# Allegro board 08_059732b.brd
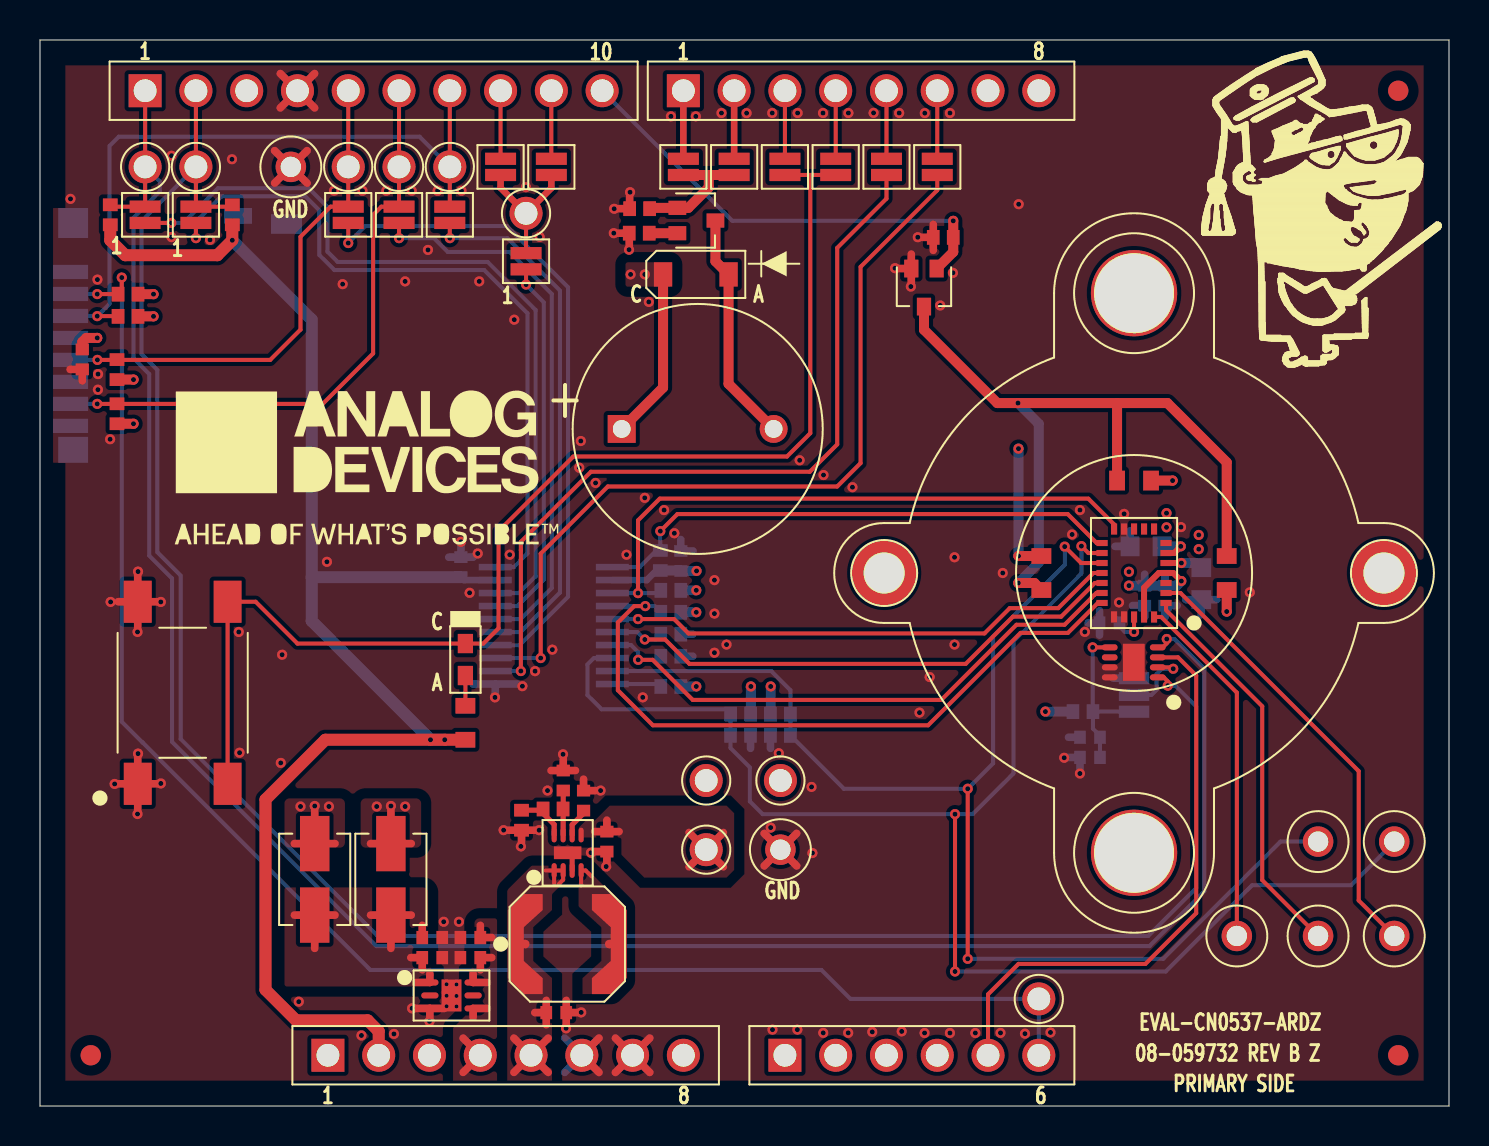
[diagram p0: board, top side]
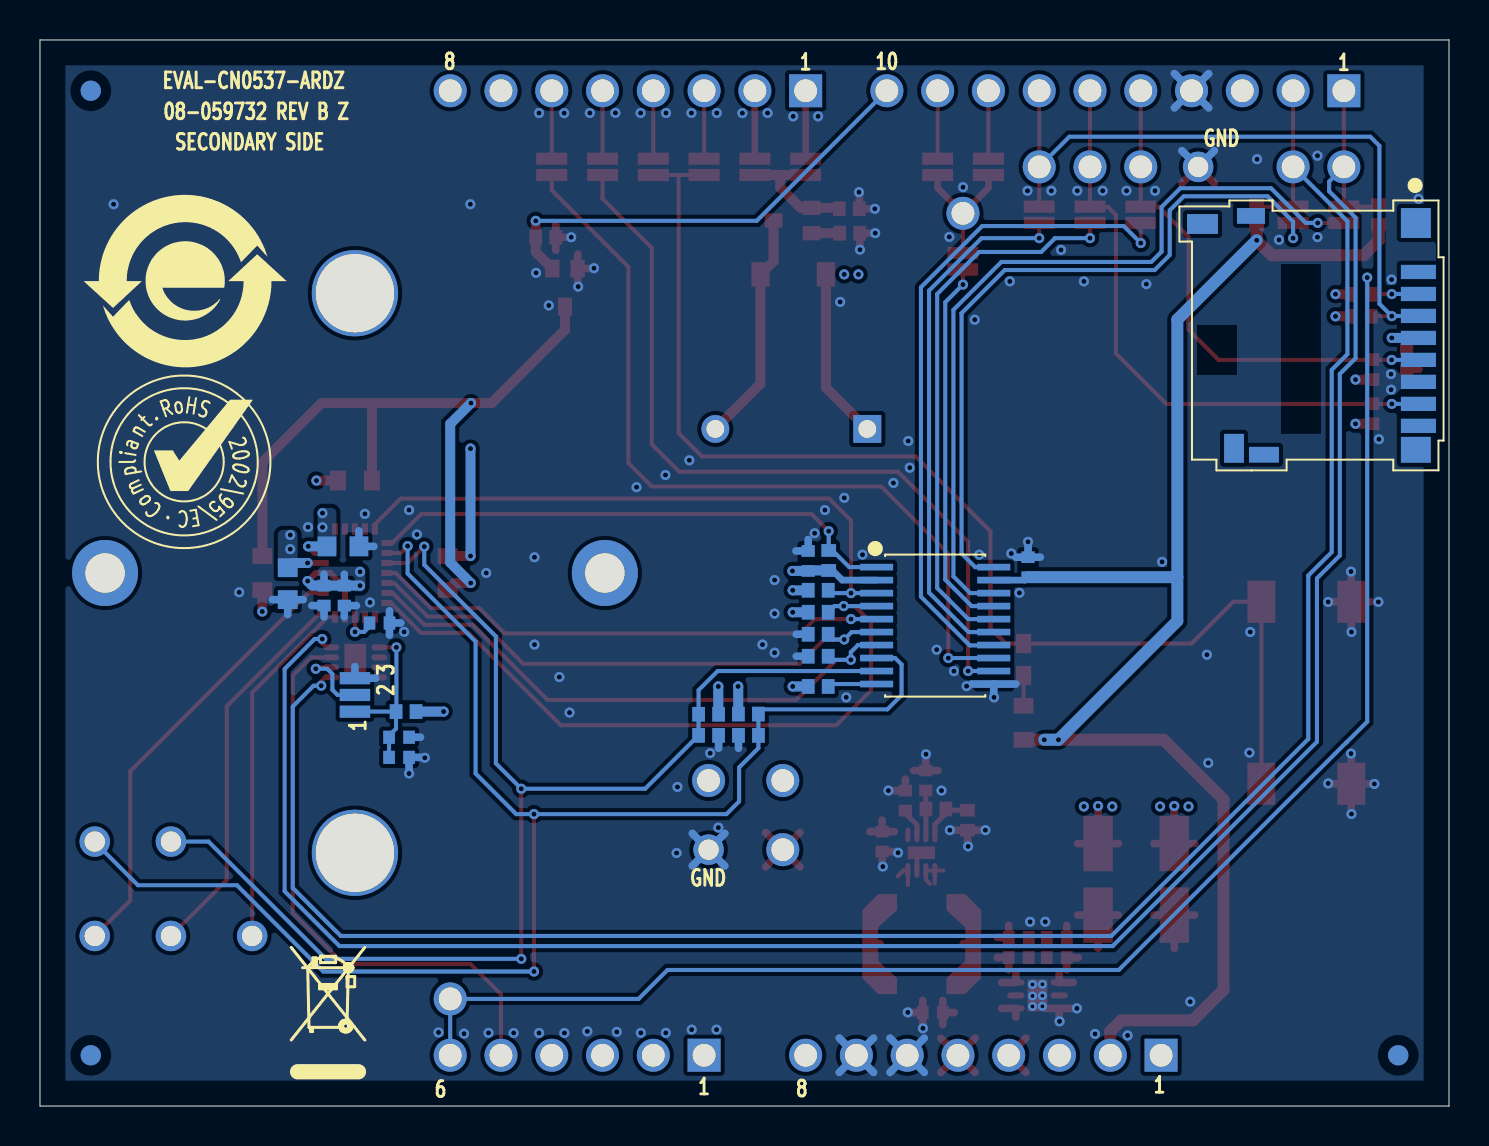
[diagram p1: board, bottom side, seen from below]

Outline 70.48 x 53.34 mm; copper layers: TOP, L2_GND, L3_PWR, BOTTOM. Coordinates in mm from the lower left corner of the outline.
Outline path: 0,53.34 0,0 70.48,0 70.48,53.34 0,53.34

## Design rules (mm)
constraint set DEFAULT: min track width 0.203

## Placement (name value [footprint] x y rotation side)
C1  10UF  [C0402]  55.26 25.54 270 bottom
C2  0.1uF  [C0402]  56.28 25.54 270 bottom
C3  22uF  [C0603]  58.09 26.14 270 bottom
C4  22uF  [C0603]  55.33 28 180 bottom
C5  1UF  [C0402]  53.5 24.17 180 bottom
C7  0.1uF  [C0402]  32.06 27.27 90 bottom
C8  0.1uF  [C0402]  21.06 26.96 90 bottom
C9  10UF  [C0402]  21.53 8.43 180 top
C10  0.1uF  [C0402]  21.53 7.43 180 top
C11  0.1uF  [C0402]  19.62 7.43 0 top
C12  10UF  [C0402]  19.62 8.43 0 top
C13  2.2uF  [C0402]  25.82 4.68 0 top
C14  0.1uF  [C0402]  27.19 15.28 90 top
C15  0.1uF  [C0402]  26.18 16.29 90 top
C16  1UF  [C0402]  28.36 13.23 270 top
C17  0.1uF  [C0402]  2.12 37.36 270 top
C18  10UF  [C0402]  52.52 17.44 180 bottom
C19  0.1uF  [C0402]  52.52 18.45 180 bottom
CS1  TESTPAD  [TPC65D45]  24.31 44.67 0 top
CS2  TESTPAD  [TPC65D45]  49.96 5.36 0 top
D2  1N4148W-7-F  [SOD123-2]  32.81 41.61 0 top
DS1  APT1608-LSECK-J3-PRV  [LED0603]  21.28 22.34 270 top
E1  42OHM AT 10MEGHZ  [LSML160W120H120]  17.55 11.34 90 top
E2  42OHM AT 10MEGHZ  [LSML160W120H120]  13.74 11.34 90 top
GND1  BLK  [CNKEY5001TP]  37.04 12.83 270 top
GND2  BLK  [CNKEY5001TP]  12.55 46.99 270 top
GPIO0  BLK  [CNKEY5001TP]  67.74 13.23 0 top
GPIO1  BLK  [CNKEY5001TP]  63.93 13.23 180 top
JP1  -  [JPSLD02]  7.8 44.59 90 top
JP2  -  [JPSLD02]  5.26 44.59 90 top
JP3  -  [JPSLD02]  24.31 42.27 90 top
JP4  -  [JPSLD02]  17.96 44.59 90 top
JP5  -  [JPSLD02]  20.5 44.59 90 top
JP6  -  [JPSLD02]  15.42 44.59 90 top
JP7  3PIN_SOLDER_JUMPER  [JPRSLD03]  54.73 20.57 90 bottom
JP12  -  [JPSLD02]  23.04 46.99 270 top
JP13  -  [JPSLD02]  25.58 46.99 270 top
JP14  -  [JPSLD02]  32.18 46.99 270 top
JP15  -  [JPSLD02]  34.72 46.99 270 top
JP16  -  [JPSLD02]  37.26 46.99 270 top
JP17  -  [JPSLD02]  39.8 46.99 270 top
JP18  -  [JPSLD02]  42.34 46.99 270 top
JP19  -  [JPSLD02]  44.88 46.99 270 top
L1  100uH  [LSMSQ189H123]  26.38 8.1 0 top
MISO  TESTPAD  [TPC65D45]  17.96 46.99 0 top
MOSI  TESTPAD  [TPC65D45]  20.5 46.99 0 top
NOREF  -  []  37.36 79.29 0 top
NOREF#2  -  []  60.69 16.84 0 top
NOREF#3  -  []  59.15 30.58 0 top
NOREF#4  -  []  14.4 2.54 0 top
NOREF#5  -  []  70.48 0 90 top
NOREF#6  -  []  70.48 53.34 180 top
NOREF#7  -  []  -143.18 -42.36 0 top
NOREF#8  -  []  56.03 42.13 0 top
NOREF#9  -  []  102.14 40.89 0 top
NOREF#10  -  [unnamed#2]  67.23 26.67 0 top
NOREF#11  -  []  59.69 336.79 0 top
NOREF#12  -  []  70.48 0 90 top
NOREF#13  -  []  24.46 253.81 0 top
NOREF#14  -  []  16.36 31.93 0 top
NOREF#15  -  []  80.7 76.07 0 top
NOREF#16  -  []  0 0 0 top
NOREF#17  -  []  56.69 40.67 0 top
NOREF#18  -  []  57.63 20.52 0 top
NOREF#19  -  []  0 53.34 0 top
NOREF#20  -  []  116.31 170.76 0 top
NOREF#21  -  [unnamed#2]  67.94 50.8 0 top
NOREF#22  -  []  0 53.34 0 top
NOREF#23  -  [unnamed#2]  67.94 2.54 0 top
NOREF#24  -  []  14.4 2.54 0 top
NOREF#25  -  [unnamed#2]  2.54 2.54 0 top
NOREF#26  -  []  75.56 0 0 top
NOREF#27  -  [unnamed#2]  54.73 12.67 0 top
NOREF#28  -  []  0 0 0 top
NOREF#29  -  []  68.11 26.22 0 top
NOREF#30  -  [unnamed#2]  54.73 40.67 0 top
NOREF#31  -  []  0 53.34 270 top
NOREF#32  -  []  62.33 20.17 0 top
NOREF#33  -  []  -41.7 -41.85 0 top
NOREF#34  -  [unnamed#2]  42.23 26.67 0 top
NOREF#35  -  []  0 0 0 top
NOREF#36  -  []  63.22 41.27 180 bottom
NOREF#37  -  []  56.28 1.4 180 bottom
NOREF#38  -  [unnamed#2]  2.54 2.54 180 bottom
NOREF#39  -  []  63.27 32.23 180 bottom
NOREF#40  -  [unnamed#2]  67.94 2.54 180 bottom
NOREF#41  -  [unnamed#2]  67.94 50.8 180 bottom
P1  SSQ-108-03-G-S  [CNSAMTECSSQ-108-XX-X-S]  14.4 2.54 0 top
P2  SSQ-106-03-G-S  [CNSAMTECSSQ-106-XX-X-S]  37.26 2.54 0 top
P3  SSQ-110-03-G-S  [CNSAMTECSSQ-110-XX-X-S]  5.26 50.8 0 top
P4  SSQ-108-03-G-S  [CNSAMTECSSQ-108-XX-X-S]  32.18 50.8 0 top
P5  DM3D-SF  [CNHIROSEDM3D-SF]  6.88 38.57 0 bottom
PD1  BLK  [CNKEY5001TP]  59.87 8.51 0 top
PD2  BLK  [CNKEY5001TP]  67.74 8.51 0 top
PDC  BLK  [CNKEY5001TP]  63.93 8.51 0 top
Q1  DMG1012UW-7  [SOT323]  44.22 40.95 180 top
Q2  DMG1012UW-7  [SOT323]  32.84 44.31 270 top
R2  51K  [R0402]  37.04 19.6 0 bottom
R3  51K  [R0402]  35.05 19.61 180 bottom
R4  51K  [R0402]  37.04 18.55 180 bottom
R5  51K  [R0402]  35.04 18.55 0 bottom
R6  25  [R0603]  54.73 31.29 180 top
R7  25  [R0603]  50.09 26.67 270 top
R9  25  [R0603]  59.36 26.67 90 top
R10  51K  [R0402]  45.18 43.46 180 top
R11  51K  [R0402]  31.03 27.3 90 bottom
R12  51K  [R0402]  31.56 25.8 180 bottom
R13  51K  [R0402]  31.56 24.7 180 bottom
R14  51K  [R0402]  31.56 20.99 180 bottom
R15  51K  [R0402]  31.56 23.6 0 bottom
R16  51K  [R0402]  31.56 22.5 0 bottom
R17  51K  [R0402]  9.62 44.59 90 top
R18  51K  [R0402]  3.52 44.59 90 top
R19  330K  [R0402]  25.67 14.86 180 top
R20  59K  [R0402]  24.09 14.3 270 top
R21  51K  [R0402]  4.4 40.62 180 top
R22  51K  [R0402]  4.4 39.51 180 top
R23  51K  [R0402]  3.85 36.85 90 top
R24  51K  [R0402]  3.85 34.64 90 top
R25  10K  [R0402]  30 44.9 180 top
R26  0  [R0402]  29.98 43.67 180 top
R27  750  [R0603]  21.28 19.18 90 top
R28  0  [R0402]  52.17 19.74 0 bottom
S1  FSM2JSMA  [SWSMSQ236H185]  7.14 20.68 0 top
SCL  TESTPAD  [TPC65D45]  5.26 46.99 0 top
SCLK  TESTPAD  [TPC65D45]  15.42 46.99 0 top
SDA  TESTPAD  [TPC65D45]  7.8 46.99 0 top
U1  ADPD188BI-ACEZ  [LGA24_A]  54.73 26.67 90 top
U3  TXB0108PWR  [TSSOP20]  25.7 24.04 270 bottom
U4  ADP151ACPZ-1.8  [DFN6_2X2_PAD1_6X1]  20.59 5.53 270 top
U5  LT8410EDC#PBF  [DFN8_2X2_PAD1_37X0_64]  26.39 12.67 0 top
U6  AI-1223-TWT-5V-5-R  [TORAD299D472H382]  29.1 33.88 0 top
U7  SHT30-DIS-B2.5KS  [DFN8_2_5X2_5_PAD1_8X1_1]  54.71 22.2 90 top
VCCA  TESTPAD  [TPC65D45]  33.33 16.29 0 top
VDD  TESTPAD  [TPC65D45]  37.04 16.29 0 top
VLED  TESTPAD  [TPC65D45]  33.33 12.83 0 top

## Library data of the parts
C1 C9 C12 C18 = CAP: User Part Number: UPN; Tolerance: 20; alternate symbols: (); part number: CAP_SM-10UF,6.3V,20,E032074,C0402; tolerance: 20
C2 C7 C8 C10 C11 C14 C15 C17 C19 = CAP: User Part Number: UPN; Tolerance: 10; alternate symbols: (); part number: CAP_SM-0.1UF,16V,10,E018707,C0402; tolerance: 10
C3 C4 = CAP: User Part Number: UPN; Tolerance: 20; alternate symbols: (); part number: CAP_SM-22UF,10V,20,E022680,C0603; tolerance: 20
C5 C16 = CAP: User Part Number: UPN; Tolerance: 10; alternate symbols: (); part number: CAP_SM-1UF,6.3V,10,E030593,C0402; tolerance: 10
C13 = CAP: User Part Number: UPN; Tolerance: 10; alternate symbols: (); part number: CAP_SM-2.2UF,6.3V,10,E021628,C0402; tolerance: 10
CS1 CS2 MISO MOSI SCL SCLK SDA VCCA VDD VLED = NCTESTPAD: Tolerance: N/A; User Part Number: UPN; alternate symbols: (); part number: NCTESTPAD_TH-TESTPAD,E013404,TPC65D45; tolerance: N/A
D2 = DIO: User Part Number: UPN; Tolerance: N/A; alternate symbols: (); part number: DIO_SM-1N4148W-7-F,100V,N/A,E018902,SOD123-2; tolerance: N/A
DS1 = DIOLED: Tolerance: N/A; User Part Number: UPN; alternate symbols: (); part number: DIOLED_SM-APT1608-LSECK-J3-PRV,1.8V,N/A,E027396,LED0603; tolerance: N/A
E1 E2 = FERRITE: Tolerance: 25; User Part Number: UPN; alternate symbols: (); part number: FERRITE_SM-42OHM AT 10MEGHZ,25,E019932,LSML160W120H120; tolerance: 25
GND1 GND2 GPIO0 GPIO1 PD1 PD2 PDC = CNTP1P: Tolerance: N/A; User Part Number: UPN; alternate symbols: (); part number: CNTP1P_TH-BLK,E005347,CNKEY5001TP; tolerance: N/A
JP1-JP6 JP12-JP19 = NC2P: User Part Number: UPN; Tolerance: N/A; alternate symbols: (); part number: NC2P_SM-JPSLD02,E006230,JPSLD02; tolerance: N/A
JP7 = NC3P_JMPR: Tolerance: N/A; User Part Number: UPN; alternate symbols: (); part number: NC3P_JMPR_SM-3PIN_SOLDER_JUMPER,E005606,JPRSLD03; tolerance: N/A
L1 = IND: User Part Number: UPN; Tolerance: 20; alternate symbols: (); part number: IND_SM-100UH,20,E022686,LSMSQ189H123; tolerance: 20
P1 P4 = CN8P_A: User Part Number: UPN; Tolerance: N/A; alternate symbols: (); part number: CN8P_A_TH-SSQ-108-03-G-S,E020478,CNSAMTECSSQ-108-XX-X-S; tolerance: N/A
P2 = CN6P: User Part Number: UPN; Tolerance: N/A; alternate symbols: (); part number: CN6P_TH-SSQ-106-03-G-S,E020477,CNSAMTECSSQ-106-XX-X-S; tolerance: N/A
P3 = CN10P: User Part Number: UPN; Tolerance: N/A; alternate symbols: (); part number: CN10P_TH-SSQ-110-03-G-S,E020479,CNSAMTECSSQ-110-XX-X-S; tolerance: N/A
P5 = CN10P_V3: User Part Number: UPN; Tolerance: N/A; alternate symbols: (); part number: CN10P_V3_SM-DM3D-SF,E021768,CNHIROSEDM3D-SF; tolerance: N/A
Q1 Q2 = TRANNMOSFET_V26: User Part Number: UPN; Tolerance: N/A; alternate symbols: (); part number: TRANNMOSFET_V26_SM-DMG1012UW-7,E032161,SOT323; tolerance: N/A
R2-R5 R10-R18 R21-R24 = RES: User Part Number: UPN; Tolerance: 1; alternate symbols: (R0402L,R0402L_ALT); part number: RES_SM-51K,E013080,1/10W,1,R0402; tolerance: 1
R6 R7 R9 = RES: User Part Number: UPN; Tolerance: 2; alternate symbols: (); part number: RES_SM-25,E042522,1.5W,2,R0603; tolerance: 2
R19 = RES: User Part Number: UPN; Tolerance: 1; alternate symbols: (R0402L); part number: RES_SM-330K,E025663,1/16W,1,R0402; tolerance: 1
R20 = RES: User Part Number: UPN; Tolerance: 1; alternate symbols: (R0402L); part number: RES_SM-59K,E026331,1/10W,1,R0402; tolerance: 1
R25 = RES: User Part Number: UPN; Tolerance: 1; alternate symbols: (R0402L,R0402L_ALT); part number: RES_SM-10K,E003751,1/10W,1,R0402; tolerance: 1
R26 R28 = RES: User Part Number: UPN; Tolerance: 5; alternate symbols: (R0402L,R0402L_ALT); part number: RES_SM-0,E003438,N/A,5,R0402; tolerance: 5
R27 = RES: User Part Number: UPN; Tolerance: 1; alternate symbols: (R0603L); part number: RES_SM-750,E029229,1/10W,1,R0603; tolerance: 1
S1 = SWSPST4PIN_B: User Part Number: UPN; Tolerance: N/A; alternate symbols: (); part number: SWSPST4PIN_B_SM-FSM2JSMA,E016530,SWSMSQ236H185; tolerance: N/A
U1 = ADPD188BI: Tolerance: N/A; User Part Number: UPN; alternate symbols: (); part number: ADPD188BI_SM-ADPD188BI-ACEZ,E032759,LGA24_A; tolerance: N/A
U3 = ICTXB0108: Tolerance: N/A; User Part Number: UPN; alternate symbols: (); part number: ICTXB0108_SM-TXB0108PWR,E019338,TSSOP20; tolerance: N/A
U4 = ADP151: User Part Number: UPN; Tolerance: N/A; alternate symbols: (); part number: ADP151_SM-ADP151ACPZ-1.8,E021940,DFN6_2X2_PAD1_6X1; tolerance: N/A
U5 = LINLT8410_X: User Part Number: UPN; Tolerance: N/A; alternate symbols: (); part number: LINLT8410_X_SM-LT8410EDC#PBF,E033623,DFN8_2X2_PAD1_37X0_64; tolerance: N/A
U6 = ICAI_1223: User Part Number: UPN; Tolerance: N/A; alternate symbols: (); part number: ICAI_1223_TH-AI-1223-TWT-5V-5-R,E030982,TORAD299D472H382; tolerance: N/A
U7 = ICSHT3X: User Part Number: UPN; Tolerance: N/A; alternate symbols: (); part number: ICSHT3X_SM-SHT30-DIS-B2.5KS,E025987,DFN8_2_5X2_5_PAD1_8X1_1; tolerance: N/A

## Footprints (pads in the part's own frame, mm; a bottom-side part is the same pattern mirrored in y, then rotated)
C0402
  rect 0.584x0.66 smd: 1(-0.5,0) 2(0.5,0)
C0603
  rect 0.94x0.991 smd: 1(-0.8,0) 2(0.8,0)
CNHIROSEDM3D-SF
  rect 1.499x1.499 smd: (-5.224,-5.612)
  rect 1.499x1.295 smd: (-5.224,5.735)
  rect 1.499x0.787 smd: (2.375,5.981)
  rect 1.397x0.787 smd: (3.025,-5.967)
  rect 1.753x0.711 smd: 1(-5.351,-3.162) 2(-5.351,-2.062) 3(-5.351,-0.962) 4(-5.351,0.138) 5(-5.351,1.238) 6(-5.351,2.338) 7(-5.351,3.438) 8(-5.351,4.538)
  rect 0.991x1.448 smd: 9(3.875,5.662)
  rect 1.549x0.991 smd: 10(5.45,-5.562)
CNKEY5001TP
  round 1.524 hole 1.016: 1(0,0)
CNSAMTECSSQ-106-XX-X-S
  rect 1.651x1.651 hole 1.143: 1(0,0)
  round 1.651 hole 1.143: 2(2.54,0) 3(5.08,0) 4(7.62,0) 5(10.16,0) 6(12.7,0)
CNSAMTECSSQ-108-XX-X-S
  rect 1.651x1.651 hole 1.143: 1(0,0)
  round 1.651 hole 1.143: 2(2.54,0) 3(5.08,0) 4(7.62,0) 5(10.16,0) 6(12.7,0) 7(15.24,0) 8(17.78,0)
CNSAMTECSSQ-110-XX-X-S
  rect 1.651x1.651 hole 1.143: 1(0,0)
  round 1.651 hole 1.143: 2(2.54,0) 3(5.08,0) 4(7.62,0) 5(10.16,0) 6(12.7,0) 7(15.24,0) 8(17.78,0) 9(20.32,0) 10(22.86,0)
DFN6_2X2_PAD1_6X1
  oval 0.305x0.864 smd: 1(-0.65,-1.082) 2(0,-1.082) 3(0.65,-1.082) 4(0.65,1.082) 5(0,1.082) 6(-0.65,1.082)
  rect 1.6x0.991 smd: PAD(0,0)
DFN8_2_5X2_5_PAD1_8X1_1
  oval 0.305x0.787 smd: 1(-0.75,-1.2) 2(-0.25,-1.2) 3(0.25,-1.2) 4(0.75,-1.2) 5(0.75,1.2) 6(0.25,1.2) 7(-0.25,1.2) 8(-0.75,1.2)
  rect 1.854x1.092 smd: PAD(0,0)
DFN8_2X2_PAD1_37X0_64
  oval 0.254x0.737 smd: 1(-0.675,-0.888) 2(-0.225,-0.888) 3(0.225,-0.888) 4(0.675,-0.888) 5(0.675,0.888) 6(0.225,0.888) 7(-0.225,0.888) 8(-0.675,0.888)
  rect 1.372x0.635 smd: PAD(0,0)
JPRSLD03
  rect 0.61x1.524 smd: 1(-0.838,0) 2(0,0) 3(0.838,0)
JPSLD02
  rect 0.61x1.549 smd: 1(-0.406,0) 2(0.406,0)
LED0603
  rect 0.965x0.762 smd: A(0.8,0) C(-0.8,0)
LGA24_A
  rect 0.305x0.559 smd: 1(-1.5,-1.6) 2(-1,-1.6) 3(-0.5,-1.6) 4(0,-1.6) 5(0.5,-1.6) 6(1,-1.6) 7(1.5,-1.6) 13(1.5,1.6) 14(1,1.6) 15(0.5,1.6) 16(0,1.6) 17(-0.5,1.6) 18(-1,1.6) 19(-1.5,1.6)
  rect 0.559x0.305 smd: 8(2.2,-1) 9(2.2,-0.5) 10(2.2,0) 11(2.2,0.5) 12(2.2,1) 20(-2.2,1) 21(-2.2,0.5) 22(-2.2,0) 23(-2.2,-0.5) 24(-2.2,-1)
LSML160W120H120
  rect 2.769x1.473 smd: 1(-1.789,0) 2(1.789,0)
LSMSQ189H123
  custom 0.435x0.435 smd: 1(-2.103,0) 2(2.103,0)
R0402
  rect 0.635x0.737 smd: 1(-0.5,0) 2(0.5,0)
R0603
  rect 0.787x0.991 smd: 1(-0.85,0) 2(0.85,0)
SOD123-2
  rect 0.914x1.219 smd: A(1.638,0) C(-1.638,0)
SOT323
  rect 0.711x0.889 smd: 1(-0.635,-0.952) 2(0.635,-0.952) 3(0,0.952)
SWSMSQ236H185
  rect 1.397x2.108 smd: 1(-2.248,-4.554) 2(-2.248,4.554) 3(2.248,-4.554) 4(2.248,4.554)
TORAD299D472H382
  round 1.397 hole 0.889: N(7.6,0)
  rect 1.397x1.397 hole 0.889: P(0,0)
TPC65D45
  round 1.651 hole 1.143: 1(0,0)
TSSOP20
  rect 0.33x1.651 smd: 1(-2.925,-2.93) 2(-2.275,-2.93) 3(-1.625,-2.93) 4(-0.975,-2.93) 5(-0.325,-2.93) 6(0.325,-2.93) 7(0.975,-2.93) 8(1.625,-2.93) 9(2.275,-2.93) 10(2.925,-2.93) 11(2.925,2.93) 12(2.275,2.93) 13(1.625,2.93) 14(0.975,2.93) 15(0.325,2.93) 16(-0.325,2.93) 17(-0.975,2.93) 18(-1.625,2.93) 19(-2.275,2.93) 20(-2.925,2.93)
unnamed#2
  round 3.302 hole 1.97 unplated: (0,0)

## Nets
1V8_VCCA: C7.1 E2.2(N2) R2.1 R3.1 R11.1 R12.1 R13.1 R14.1 U3.2 VCCA.1(N1)
1V8_VDD: C1.1 C2.1 E1.2(N2) U1.4 U1.23 VDD.1(N1)
3V3_SUPPLY: C4.1 C9.1 C10.1 C17.1 P1.4 P5.4 R21.1 R22.1 R23.1 R24.1 R28.1 U1.6 U4.4 U4.6
5V_SUPPLY: C13.1 D2.C L1.1 P1.5 R6.1 R7.1 R9.1 U5.1 U5.2 U6.P
6V_VLED: C3.1 C16.1 U1.5 U5.5 VLED.1(N1)
GND: C1.2(N2) C2.2(N2) C3.2(N2) C4.2(N2) C5.2(N2) C7.2(N2) C8.2(N2) C9.2(N2) C10.2(N2) C11.2(N2) C12.2(N2) C13.2(N2) C14.2(N2) C15.2(N2) C16.2(N2) C17.2(N2) C18.2(N2) C19.2(N2) GND1.1(N1) GND2.1(N1) JP7.3 P1.6 P1.7 P3.4 P5.6 Q1.2(S) R4.2(N2) R5.2(N2) R10.2(N2) R15.2(N2) R16.2(N2) R20.2(N2) R25.2(N2) R26.2(N2) S1.1 S1.2 U1.11 U1.20 U1.21 U3.11 U4.3 U4.PAD U5.3 U5.PAD U7.7 U7.8(VSS) U7.PAD
ADPD188BI_INT0: JP19.2(N2) U3.13
ADPD188BI_INT1: JP18.2(N2) U3.12
BUZZER_EN: JP14.2(N2) JP15.2(N2) Q2.1 R25.1
HEATER_EN: P3.10 Q1.1 R10.1
I2C_SCL_MCU: JP2.2(N2) P3.1 R18.2(N2) SCL.1(N1) U7.4
I2C_SDA_MCU: JP1.2(N2) P3.2 R17.2(N2) SDA.1(N1) U7.1
IOREF: C8.1 P1.2 R17.1 R18.1 R27.1 U3.19(VCCB)
LED_BUTTON_EN: DS1.C JP16.2(N2) JP17.2(N2) S1.3 S1.4(N4)
RH/T_SENSOR_INT: P2.5 U7.3
SPI_CS1_MCU: CS1.1(N1) JP3.2(N2) JP12.2(N2) JP13.2(N2)
SPI_CS2_MCU: CS2.1(N1) P2.6(N6) P5.2 R21.2(N2)
SPI_MISO_MCU: JP4.2(N2) MISO.1(N1) P3.6 P5.7 R24.2(N2)
SPI_MOSI_MCU: JP5.2(N2) MOSI.1(N1) P3.7 P5.3 R22.2(N2)
SPI_SCLK_MCU: JP6.2(N2) P3.5 P5.5 R23.2(N2) SCLK.1(N1)
UNNAMED_2_ADPD188BI_I1_CSN: R13.2(N2) U1.19 U3.4
UNNAMED_2_ADPD188BI_I1_EXTIN1: PD1.1(N1) U1.24
UNNAMED_2_ADPD188BI_I1_EXTIN2: PD2.1(N1) U1.2
UNNAMED_2_ADPD188BI_I1_GPIO0: GPIO0.1(N1) R3.2(N2) R5.1 U1.14 U3.8
UNNAMED_2_ADPD188BI_I1_GPIO1: GPIO1.1(N1) R2.2(N2) R4.1 U1.15 U3.9
UNNAMED_2_ADPD188BI_I1_MISO: U1.16 U3.5
UNNAMED_2_ADPD188BI_I1_MOSI: R15.1 U1.17 U3.6
UNNAMED_2_ADPD188BI_I1_PDC: PDC.1(N1) U1.1
UNNAMED_2_ADPD188BI_I1_SCL: R12.2(N2) U1.12 U3.3
UNNAMED_2_ADPD188BI_I1_SCLK: R16.1 U1.18 U3.7
UNNAMED_2_ADPD188BI_I1_SDA: R11.2(N2) U1.13 U3.1
UNNAMED_2_ADPD188BI_I1_VREF: C5.1 U1.22(VREF)
UNNAMED_2_ICTXB0108_I206_B1: JP1.1 U3.20
UNNAMED_2_ICTXB0108_I206_B2: JP2.1 U3.18
UNNAMED_2_ICTXB0108_I206_B3: JP3.1 U3.17
UNNAMED_2_ICTXB0108_I206_B4: JP4.1 U3.16
UNNAMED_2_ICTXB0108_I206_B5: JP5.1 U3.15
UNNAMED_2_ICTXB0108_I206_B6: JP6.1 U3.14
UNNAMED_2_ICTXB0108_I206_OE: R14.2(N2) U3.10
UNNAMED_2_RES_I246_N2: Q1.3 R6.2(N2) R7.2(N2) R9.2(N2)
UNNAMED_3_CN8PA_I130_N1: JP14.1 P4.1
UNNAMED_3_CN8PA_I130_N2: JP15.1 P4.2
UNNAMED_3_CN8PA_I130_N3: JP16.1 P4.3
UNNAMED_3_CN8PA_I130_N4: JP17.1 P4.4
UNNAMED_3_CN8PA_I130_N5: JP18.1 P4.5
UNNAMED_3_CN8PA_I130_N6: JP19.1 P4.6
UNNAMED_3_CN10P_I2_N8: JP12.1 P3.8
UNNAMED_3_CN10P_I2_N9: JP13.1 P3.9(N9)
UNNAMED_3_DIO_I112_P: D2.A(P) Q2.3 U6.N(N2)
UNNAMED_3_DIOLED_I99_P: DS1.A(P) R27.2(N2)
UNNAMED_3_RES_I129_N1: Q2.2(S) R26.1
UNNAMED_5_ADP151_I10_VOUT: C11.1 C12.1 E1.1 E2.1 U4.1(VOUT)
UNNAMED_5_CAP_I57_N1: C14.1 U5.6
UNNAMED_5_CAP_I62_N1: C15.1 R19.1 U5.7(VREF)
UNNAMED_5_IND_I56_N2: L1.2(N2) U5.4
UNNAMED_5_LINLT8410X_I52_FBP: R19.2(N2) R20.1 U5.8
UNNAMED_6_CAP_I7_N1: C18.1 C19.1 JP7.1 R28.2(N2) U7.5
UNNAMED_6_ICSHT3X_I6_ADDR: JP7.2(COM) U7.2

Pads without a net: P1 1 3 8; P2 1 2 3 4; P3 3; P4 7 8; P5 1 8 9 10; U1 3 7 8 9 10; U4 2 5; U7 6

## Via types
v1: diameter 0.508, hole 0.254, TOP to BOTTOM, 198 vias
v2: diameter 0.457, hole 0.203, TOP to BOTTOM, 6 vias

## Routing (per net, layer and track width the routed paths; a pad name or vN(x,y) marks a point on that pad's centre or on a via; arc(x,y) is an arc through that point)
1V8_VCCA: length 47.2
  TOP w0.381: 12.73,13.13 E2.2 ; E2.2 14.76,13.13 ; E2.2 13.74,14.79
  L3_PWR w0.9: v1(32.83,20.99) 32.83,19.55 33.33,19.05 VCCA.1 30.76,16.29 30.35,16.69 14.92,16.69 14.24,16.01 ; v1(32.83,20.99) v1(35.56,20.99) v1(36.55,20.99) ; v1(32.83,20.99) v1(32.83,24.7) v1(32.83,25.8) 32.83,26.76 v1(32.84,26.77)
  BOTTOM w0.33: R11.1 30.84,26.8 30.35,26.31 U3.2
  BOTTOM w0.5: R2.1 36.55,19.61 v1(36.55,20.99) ; R13.1 v1(32.83,24.7) ; v1(35.56,20.99) 35.55,20.99 35.55,19.62 R3.1 ; v1(32.84,26.77) C7.1 32.03,26.8 R11.1 ; R12.1 v1(32.83,25.8) ; R14.1 v1(32.83,20.99)
  vias: v1(13.03,14.99) v1(13.74,15.01) v1(14.45,14.99)
1V8_VDD: length 53
  TOP w0.3: U1.23 55.23,25.93 55.97,26.67 U1.4 56.69,26.67 v1(57.09,26.27)
  TOP w0.381: E1.2 17.55,14.79 ; E1.2 16.54,13.13 ; E1.2 18.57,13.13
  L3_PWR w0.9: 54.12,26.38 54.14,26.38 v1(54.47,26.04) v1(54.47,26.73) 54.12,26.38 ; 54.12,26.38 52.64,26.38 44.93,18.67 39.5,18.67 37.12,16.29 VDD.1 35.36,14.61 30.04,14.61 29.77,14.88 19.17,14.88
  BOTTOM w0.381: C1.1 55.26,26.61 ; C2.1 56.28,26.61
  BOTTOM w0.5: v1(57.09,26.27) 56.87,26.04 C2.1 C1.1 v1(54.47,26.04)
  vias: v1(16.84,14.99) v1(17.56,15.01) v1(18.27,14.99)
3V3_SUPPLY: length 18.4
  TOP w0.3: U1.6 56.73,27.67 v1(57.06,28)
  TOP w0.381: 21.17,1.68 P1.4 21.17,3.4 ; 22.38,4.88 U4.4 21.67,4.45 ; 22.38,6.18 U4.6 21.67,6.61 ; 22.03,9.04 C9.1 22.6,8.43 ; 22.03,6.82 C10.1 22.6,7.43
  TOP w0.5: R22.1 v1(5.68,39.51) ; R21.1 v1(5.68,40.62) ; R24.1 v1(4.68,34.14) ; R23.1 v1(4.68,36.35) ; v1(2.86,38.43) 2.32,38.43 2.12,38.23 C17.1
  L3_PWR w0.381: 21.17,1.68 P1.4 21.17,3.4
  BOTTOM w0.5: v1(57.06,28) C4.1 ; v1(50.29,19.74) R28.1 ; P5.4 v1(2.86,38.43)
  vias: v1(56.35,29.67) v1(56.35,28.96)
5V_SUPPLY: length 31
  TOP w0.203: U5.1 U5.2 26.17,11.32 25.96,11.12 ; U5.1 25.3,11.78 ; U5.1 25.72,11.12
  TOP w0.254: R6.1 55.68,31.29
  TOP w0.381: 24.75,4.68 C13.1 ; C13.1 25.32,5.29 ; C13.1 25.32,4.07 ; P1.5 25.42,1.68 ; P1.5 23.71,3.4 ; P1.5 25.42,3.4 ; P1.5 23.71,1.68
  TOP w0.5: D2.C 31.17,35.95 U6.P ; 55.68,31.29 v1(56.66,31.29) ; R9.1 v1(59.36,24.74) ; R7.1 v1(48.95,27.52)
  L3_PWR w0.381: 23.71,1.68 P1.5 ; P1.5 25.42,1.68 ; P1.5 23.71,3.4 ; P1.5 25.42,3.4
  BOTTOM w0.5: v1(48.95,27.52) v1(48.95,32.89)
  vias: v1(29.54,41.61) v1(30.25,41.61)
6V_VLED: length 44.9
  TOP w0.3: U1.5 v1(57.1,27.17)
  TOP w0.381: 32.47,11.97 VLED.1 ; VLED.1 34.18,11.97 ; VLED.1 32.47,13.68 ; VLED.1 34.18,13.68 ; C16.1 28.36,14.3 ; C16.1 28.97,13.73 ; C16.1 27.75,13.73
  L3_PWR w0.9: VLED.1 35.49,10.67 48.28,10.67 58.11,20.5 58.11,27.1
  BOTTOM w0.5: C3.1 57.86,27.17 v1(57.1,27.17)
  vias: v1(57.97,28.57) v1(57.97,27.86)
GND: length 113.5
  TOP w0.25: U5.PAD 26.62,12.45 U5.3
  TOP w0.381: S1.1 4.89,17.46 ; S1.1 3.91,16.12 ; S1.1 4.89,14.79 ; S1.1 5.87,16.12 ; 25.57,16.79 C15.2 ; C15.2 26.18,17.36 ; C15.2 26.78,16.79 ; GND2.1 13.36,46.18 ; GND2.1 13.36,47.8 ; GND2.1 11.74,47.8 ; GND2.1 11.74,46.18 ; 12.02,49.94 P3.4 ; P3.4 13.74,49.94 ; P3.4 12.02,51.66 ; P3.4 13.74,51.66 ; 28.88,43.67 R26.2 29.48,43.03 ; 27.75,12.73 C16.2 28.36,12.16 ; 23.44,13.8 R20.2 ; R20.2 24.09,13.2 ; R20.2 24.74,13.8 ; 29.5,45.55 R25.2 28.9,44.9 ; 42.95,41.9 Q1.2 ; Q1.2 43.59,42.63 ; Q1.2 43.59,41.18 ; GND1.1 37.85,13.64 ; GND1.1 36.23,12.01 ; GND1.1 36.23,13.64 ; GND1.1 37.85,12.01 ; 27.8,15.78 C14.2 27.19,16.35 ; C13.2 26.32,5.29 ; C13.2 26.32,4.07 ; C13.2 26.9,4.68 ; 1.51,36.86 C17.2 2.12,36.29 ; 18.79,4.88 U4.3 ; U4.3 20.21,4.88 ; U4.3 19.5,4.45 ; 28.79,1.68 P1.7 ; P1.7 30.5,3.4 ; P1.7 30.5,1.68 ; P1.7 28.79,3.4 ; 4.89,23.9 S1.2 ; S1.2 3.91,25.23 ; S1.2 4.89,26.56 ; S1.2 5.87,25.23 ; 44.09,43.46 R10.2 ; R10.2 44.68,42.82 ; R10.2 44.68,44.11 ; 27.96,3.4 P1.6 27.96,1.68
  L2_GND w0.381: 26.25,1.68 P1.6 ; P1.6 26.25,3.4 ; P1.6 27.96,1.68 ; P1.6 27.96,3.4 ; GND1.1 37.85,13.64 ; GND1.1 36.23,12.01 ; GND1.1 37.85,12.01 ; GND1.1 36.23,13.64 ; GND2.1 13.36,46.18 ; GND2.1 11.74,46.18 ; GND2.1 13.36,47.8 ; GND2.1 11.74,47.8 ; 28.79,1.68 P1.7 ; P1.7 30.5,3.4 ; P1.7 28.79,3.4 ; P1.7 30.5,1.68 ; P3.4 13.74,49.94 ; P3.4 13.74,51.66 ; P3.4 12.02,51.66 ; P3.4 12.02,49.94
  BOTTOM w0.381: P3.4 13.74,49.94 ; P3.4 12.02,51.66 ; P3.4 12.02,49.94 ; P3.4 13.74,51.66 ; P1.6 27.96,1.68 ; P1.6 26.25,3.4 ; P1.6 26.25,1.68 ; P1.6 27.96,3.4 ; 28.79,1.68 P1.7 ; P1.7 30.5,3.4 ; P1.7 30.5,1.68 ; P1.7 28.79,3.4 ; 51.45,18.45 C19.2 ; 53.69,21.41 JP7.3 54.73,21.99 ; 22.77,20.67 U3.11 ; U3.11 21.67,21.11 ; U3.11 23.88,21.11 ; C8.2 21.67,27.46 ; C8.2 21.06,28.03 ; C8.2 20.45,27.46 ; 54.65,25.04 C1.2 55.26,24.47 ; 36.54,17.9 R4.2 ; C5.2 53,24.78 ; C5.2 52.43,24.17 ; C5.2 53,23.56 ; 57.32,25.34 C3.2 ; C3.2 58.09,24.59 ; C3.2 58.87,25.34 ; 11.74,47.8 GND2.1 13.36,47.8 ; GND1.1 37.85,12.01 ; GND1.1 37.85,13.64 ; GND1.1 36.23,13.64 ; GND1.1 36.23,12.01 ; 52.02,16.83 C18.2 51.45,17.44 ; 32.06,28.34 C7.2 32.67,27.77 ; 56.88,25.04 C2.2 56.28,24.47 ; 53.78,28 C4.2 54.53,28.78 ; R16.2 32.65,22.5 ; R15.2 32.65,23.6 ; 35.54,17.9 R5.2
  vias: v1(1.53,45.39) v1(2.87,41.35) v1(2.9,36.62) v1(2.9,35.84) v1(3.51,33.36) v1(3.53,25.22) v1(3.73,16.11) v1(4.9,26.74) v1(4.88,23.72) v1(4.9,17.63) v1(4.88,14.61) v1(6.05,25.22) v1(6.05,16.14) v1(6.58,47.55) v1(6.58,43.48) v1(8.51,43.34) v1(9.6,47.37) v1(9.94,23.72) v1(9.98,17.68) v1(12.04,17.17) v1(12.11,22.58) v1(12.95,5.22) v1(14.35,27.23) v1(14.71,45.8) v1(15.14,41.12) v1(16.13,45.8) v1(16.08,3.53) v1(17.32,45.8) v1(17.71,3.61) v1(18.26,41.26) v1(18.59,45.8) v1(18.61,4.89) v1(19.41,42.84) v1(19.48,4.24) v1(19.89,45.8) v1(20.2,9.22) v1(20.96,9.22) v1(21.08,45.8) v1(21.06,28.23) v1(21.49,25.68) v1(21.9,27.65) v1(21.97,41.26) v1(22.76,20.45) v1(23.19,13.8) v1(23.5,27.59) v1(23.73,39.34) v1(24.13,21.01) v1(24.06,12.99) v1(24.31,45.97) v1(24.77,21.76) v1(25,43.48) v1(24.97,13.8) v1(25.39,15.78) v1(25.63,22.83) v1(26.16,17.6) v1(26.32,3.89) v1(27.05,33.27) v1(26.98,31.94) v1(27.07,4.68) v1(27.56,12.67) v1(27.79,31.18) v1(28.04,15.78) v1(28.32,11.98) v1(28.72,44.89) v1(28.7,43.67) v1(29.34,27.59) v1(29.52,45.72) v1(29.47,42.85) v1(30.15,20.45) v1(30.25,30.43) v1(30.46,40.23) v1(31.22,29.82) v1(31.56,49.52) v1(31.73,28.66) v1(32.81,49.52) v1(33.74,26.31) v1(33.74,24.64) v1(33.74,22.68) v1(34.09,49.69) v1(34.34,23.09) v1(35.35,49.68) v1(36.55,13.93) v1(36.63,49.69) v1(36.64,3.82) v1(36.96,17.65) v1(37.9,49.69) v1(37.89,3.82) v1(38,32.31) v1(38.6,15.97) v1(38.64,12.66) v1(39.17,49.69) v1(39.19,31.57) v1(39.18,3.66) v1(40.44,49.69) v1(40.43,3.66) v1(40.64,30.96) v1(41.63,3.71) v1(41.7,49.69) v1(42.77,41.92) v1(42.98,49.69) v1(43.11,3.73) v1(43.56,41) v1(43.91,43.47) v1(44,19.68) v1(44.25,3.65) v1(44.26,49.68) v1(44.5,21.46) v1(45.03,40.06) v1(45.52,49.69) v1(45.52,3.65) v1(45.67,41.69) v1(45.75,27.46) v1(45.75,23.09) v1(46.79,3.65) v1(48.05,3.66) v1(48.16,26.67) v1(48.96,45.12) v1(49.27,3.62) v1(50.55,3.68) v1(51.23,17.42) v1(51.63,28.6) v1(52.02,29.82) v1(52.02,16.64) v1(52.27,23.72) v1(53.98,25.2) v1(54.23,29.63) v1(57.08,28.97) v1(60.52,25.7) v1(66.8,45.12) v2(20.34,6.09) v2(20.34,5.52) v2(20.34,4.99) v2(20.84,6.08) v2(20.84,5.51) v2(20.84,4.98)
ADPD188BI_INT0: length 41.4
  TOP w0.203: JP19.2 44.88,45.82 41.05,41.99 41.05,32.17 39.88,31 28.41,31 25.05,27.64 v1(25.05,22.41)
  BOTTOM w0.203: U3.13 v1(25.05,22.41)
ADPD188BI_INT1: length 40.1
  TOP w0.203: JP18.2 42.34,45.4 39.88,42.94 39.88,33.11 38.51,31.74 27.56,31.74 24.06,28.23 24.06,27.82 v1(24.06,21.76)
  BOTTOM w0.203: U3.12 v1(24.06,21.76)
BUZZER_EN: length 6.6
  TOP w0.5: 33.45,46.58 JP15.2 ; 33.45,46.58 JP14.2 ; 33.45,46.58 33.45,45.96 32.44,44.94 Q2.1 30.54,44.94 R25.1
HEATER_EN: length 23
  TOP w0.5: Q1.1 45.68,42.73 R10.1 v1(45.68,44.29)
  BOTTOM w0.203: P3.10 34.63,44.29 v1(45.68,44.29)
I2C_SCL_MCU: length 109.4
  TOP w0.203: U7.4 56.16,22.95 56.36,23.15 v1(56.36,23.37) ; P3.1 SCL.1 JP2.2 3.61,45 R18.2
  BOTTOM w0.203: v1(56.36,23.37) 56.75,23.37 58.24,21.87 58.24,10.74 55.5,8 16.83,8 6.61,18.22 6.61,26.4 5.46,27.54 5.46,36.63 4.68,37.41 4.68,44.45 6,45.77 6,46.25 SCL.1
I2C_SDA_MCU: length 105.8
  TOP w0.203: v1(56.42,21.03) 56.42,21.25 56.21,21.45 U7.1 ; R17.2 9.53,45 JP1.2 SDA.1 P3.2
  BOTTOM w0.203: SDA.1 5.08,44.27 5.08,37.62 5.87,36.83 5.87,27.71 7.04,26.54 7.04,18.36 16.89,8.51 55.44,8.51 57.84,10.91 57.84,19.99 56.8,21.03 v1(56.42,21.03)
IOREF: length 75.8
  TOP w0.6: R18.1 3.52,43.32 4.26,42.57 8.87,42.57 v1(9.62,43.32) R17.1 ; P1.2 16.94,3.74 16.39,4.29 12.81,4.29 11.28,5.82 11.28,15.33 14.27,18.33 v1(19.53,18.33) v1(20.25,18.33) R27.1
  BOTTOM w0.33: U3.19 21.2,26.31 C8.1
  BOTTOM w0.6: 13.59,26.46 13.59,39.35 v1(9.62,43.32) ; 13.59,26.46 C8.1 ; 13.59,26.46 13.59,24.27 v1(19.53,18.33) v1(20.25,18.33)
LED_BUTTON_EN: length 61.8
  TOP w0.203: 38.53,46.58 JP16.2 ; 38.53,46.58 38.53,33.67 37.37,32.5 26.68,32.5 22.94,28.76 22.94,23.9 22.18,23.14 DS1.C 12.88,23.14 10.79,25.23 S1.4 S1.3 ; 38.53,46.58 JP17.2
RH/T_SENSOR_INT: length 29.3
  TOP w0.203: U7.3 56.93,22.45 57.84,21.54 57.84,9.65 55.3,7.11 48.95,7.11 47.42,5.59 P2.5
SPI_CS1_MCU: length 6.9
  TOP w0.203: CS1.1 JP3.2
  TOP w0.33: JP13.2 25.58,45.93 CS1.1 23.04,45.94 JP12.2
SPI_CS2_MCU: length 79.9
  TOP w0.203: v1(2.86,40.63) 3.9,40.63 R21.2 4.09,40.81 v1(4.09,41.45)
  BOTTOM w0.203: v1(4.09,41.45) 4.09,19.23 5.13,18.19 5.14,18.19 16.52,6.81 39.09,6.81 40.54,5.36 CS2.1 P2.6 ; v1(2.86,40.63) 2.86,40.63 P5.2
SPI_MISO_MCU: length 30.4
  TOP w0.203: v1(2.86,35.13) 3.85,35.13 R24.2 3.86,35.13 14.14,35.13 16.66,37.65 16.66,44.59 17.07,45 JP4.2 17.96,45 MISO.1 P3.6
  BOTTOM w0.203: P5.7 v1(2.86,35.13)
SPI_MOSI_MCU: length 34.8
  TOP w0.203: v1(2.86,39.52) 3.89,39.52 R22.2 ; P3.7 MOSI.1 JP5.2
  BOTTOM w0.203: P5.3 2.85,39.53 v1(2.86,39.52) 3.48,40.14 3.48,48.04 3.94,48.5 18.99,48.5 MOSI.1
SPI_SCLK_MCU: length 25.6
  TOP w0.203: P3.5 SCLK.1 JP6.2 14.53,45 13.03,43.5 13.03,38.85 11.52,37.33 3.87,37.33 R23.2 3.84,37.33 v1(2.87,37.33)
  BOTTOM w0.203: P5.5 v1(2.87,37.33)
UNNAMED_2_ADPD188BI_I1_CSN: length 35.1
  TOP w0.203: v1(30.28,25.01) 29.73,25.01 28.91,24.2 28.91,20.8 30.66,19.05 44.43,19.05 49.05,23.67 51.42,23.67 52.92,25.17 U1.19
  BOTTOM w0.203: U3.4 v1(30.28,25.01) 30.75,25.01 R13.2
UNNAMED_2_ADPD188BI_I1_EXTIN1: length 17.9
  TOP w0.203: PD1.1 59.87,20.69 56.09,24.47 U1.24
UNNAMED_2_ADPD188BI_I1_EXTIN2: length 22.3
  TOP w0.203: PD2.1 65.97,10.29 65.97,16.75 57.05,25.67 U1.2
UNNAMED_2_ADPD188BI_I1_GPIO0: length 76
  TOP w0.203: U1.14 52.44,27.67 v1(52.09,28.02) ; v1(45.77,6.73) v1(45.77,14.61)
  BOTTOM w0.203: U3.8 27.71,22.41 27.38,22.09 27.38,20.56 28.09,19.85 34.31,19.85 R3.2 34.55,18.55 R5.1 34.54,17.91 35.51,16.94 35.51,15.24 36.15,14.61 v1(45.77,14.61) 46.66,14.61 48.69,16.64 48.69,23.24 52.09,26.64 v1(52.09,28.02) ; GPIO0.1 67.74,13.21 65.58,11.05 60.63,11.05 56.31,6.73 v1(45.77,6.73)
UNNAMED_2_ADPD188BI_I1_GPIO1: length 66.3
  TOP w0.203: v1(51.26,27.99) 52.08,27.17 U1.15 ; v1(46.41,7.37) v1(46.41,15.88)
  BOTTOM w0.203: v1(51.26,27.99) 51.26,27.08 47.68,23.49 47.68,17.14 v1(46.41,15.88) 40.21,15.88 R4.1 R2.2 37.54,20.81 36.58,21.76 U3.9 ; GPIO1.1 62.05,13.23 56.19,7.37 v1(46.41,7.37)
UNNAMED_2_ADPD188BI_I1_MISO: length 26
  TOP w0.203: U1.16 52.69,26.67 50.94,24.91 48.51,24.91 47.25,23.65 32.44,23.65 31.72,24.36 v1(29.92,24.36)
  BOTTOM w0.203: U3.5 v1(29.92,24.36)
UNNAMED_2_ADPD188BI_I1_MOSI: length 27.7
  TOP w0.203: v1(30.25,23.34) 31.27,23.34 32.49,22.12 46.31,22.12 48.67,24.49 51.08,24.49 52.77,26.17 U1.17
  BOTTOM w0.203: U3.6 29.88,23.71 v1(30.25,23.34) 30.79,23.34 R15.1
UNNAMED_2_ADPD188BI_I1_PDC: length 19.8
  TOP w0.203: U1.1 56.33,24.81 61.14,20 61.14,11.3 PDC.1
UNNAMED_2_ADPD188BI_I1_SCL: length 31.1
  TOP w0.203: U1.12 53.73,29.1 52.44,30.39 31,30.39 29.92,29.3 v1(29.92,25.66)
  BOTTOM w0.203: U3.3 v1(29.92,25.66) 30.92,25.66 R12.2
UNNAMED_2_ADPD188BI_I1_SCLK: length 29.3
  TOP w0.203: U1.18 52.84,25.67 52.75,25.58 52.74,25.58 52.6,25.43 52.6,25.42 51.25,24.08 48.85,24.08 45.09,20.32 32.65,20.32 30.65,22.33 v1(29.92,22.33)
  BOTTOM w0.203: R16.1 30.88,22.33 v1(29.92,22.33) 29.92,22.71 29.57,23.06 U3.7
UNNAMED_2_ADPD188BI_I1_SDA: length 26.8
  TOP w0.203: U1.13 52.86,28.17 51.41,29.62 31.88,29.62 v1(31.03,28.76)
  BOTTOM w0.203: U3.1 30,26.96 30.84,27.8 R11.2 v1(31.03,28.76)
UNNAMED_2_ADPD188BI_I1_VREF: length 1.8
  TOP w0.203: U1.22 v1(54.73,23.72)
  BOTTOM w0.203: C5.1 54,23.99 54.27,23.72 v1(54.73,23.72)
UNNAMED_2_ICTXB0108_I206_B1: length 36.3
  TOP w0.203: JP1.1 v1(7.8,43.42)
  BOTTOM w0.203: v1(7.8,43.42) 7.8,44.25 9.07,45.52 13.27,45.52 13.97,44.82 13.97,42.58 14.73,41.83 22.22,41.83 24.39,39.66 24.39,27.65 23.7,26.96 U3.20
UNNAMED_2_ICTXB0108_I206_B2: length 39.8
  TOP w0.203: v1(6.57,44.19) JP2.1
  BOTTOM w0.203: U3.18 23.95,25.66 24.79,26.5 24.79,39.83 22.39,42.23 14.89,42.23 14.38,42.75 14.38,44.98 13.44,45.92 8.9,45.92 7.17,44.19 v1(6.57,44.19)
UNNAMED_2_ICTXB0108_I206_B3: length 18.9
  TOP w0.203: JP3.1 v1(24.31,41.1)
  BOTTOM w0.203: v1(24.31,41.1) 25.2,40.22 25.2,26.34 23.88,25.01 U3.17
UNNAMED_2_ICTXB0108_I206_B4: length 27.8
  TOP w0.203: JP4.1 v1(17.96,43.42)
  BOTTOM w0.203: U3.16 24.05,24.36 25.6,25.92 25.6,40.63 23.5,42.73 20.4,42.73 19.71,43.42 v1(17.96,43.42)
UNNAMED_2_ICTXB0108_I206_B5: length 26.5
  TOP w0.203: JP5.1 v1(20.5,43.42)
  BOTTOM w0.203: U3.15 24.04,23.71 26.01,25.69 26.01,40.8 23.39,43.42 v1(20.5,43.42)
UNNAMED_2_ICTXB0108_I206_B6: length 33.8
  TOP w0.203: JP6.1 v1(15.42,43.18)
  BOTTOM w0.203: v1(15.42,43.18) 16.27,44.03 23.35,44.03 26.42,40.97 26.42,25.49 23.98,23.05 22.79,23.05 U3.14
UNNAMED_2_ICTXB0108_I206_OE: length 2.5
  BOTTOM w0.203: U3.10 30.93,21.11 R14.2
UNNAMED_2_RES_I246_N2: length 38.8
  TOP w0.5: R6.2 53.88,35.15 53.9,35.17 ; Q1.3 44.22,38.84 47.89,35.17 v1(48.92,35.17) 53.9,35.17 ; R9.2 59.36,32.21 56.4,35.17 53.9,35.17 ; v1(48.94,26.17) 49.74,26.17 R7.2
  BOTTOM w0.5: v1(48.94,26.17) 49.96,27.19 49.96,34.13 v1(48.92,35.17)
UNNAMED_3_CN8PA_I130_N1: length 3.4
  TOP w0.33: P4.1 JP14.1
UNNAMED_3_CN8PA_I130_N2: length 3.4
  TOP w0.33: P4.2 JP15.1
UNNAMED_3_CN8PA_I130_N3: length 3.4
  TOP w0.203: JP16.1 P4.3
UNNAMED_3_CN8PA_I130_N4: length 3.4
  TOP w0.203: JP17.1 P4.4
UNNAMED_3_CN8PA_I130_N5: length 3.4
  TOP w0.203: JP18.1 P4.5
UNNAMED_3_CN8PA_I130_N6: length 3.4
  TOP w0.203: JP19.1 P4.6
UNNAMED_3_CN10P_I2_N8: length 3.4
  TOP w0.203: P3.8 JP12.1
UNNAMED_3_CN10P_I2_N9: length 3.4
  TOP w0.203: JP13.1 P3.9
UNNAMED_3_DIO_I112_P: length 11.6
  TOP w0.5: U6.N 34.44,36.13 D2.A 33.79,42.27 Q2.3
UNNAMED_3_DIOLED_I99_P: length 1.5
  TOP w0.203: R27.2 DS1.A
UNNAMED_3_RES_I129_N1: length 1.4
  TOP w0.5: Q2.2 30.48,43.67 R26.1
UNNAMED_5_ADP151_I10_VOUT: length 10.3
  TOP w0.381: 18.79,6.18 U4.1 19.5,6.61 ; E1.1 18.57,9.55 ; E1.1 17.55,7.89 ; E1.1 16.54,9.55 ; 12.73,9.55 E2.1 ; E2.1 14.76,9.55 ; E2.1 13.74,7.89 ; C12.1 19.12,9.04 ; 19.12,6.82 C11.1 18.55,7.43
UNNAMED_5_CAP_I57_N1: length 1.5
  TOP w0.254: C14.1 27.19,14.64 26.62,14.07 U5.6
UNNAMED_5_CAP_I62_N1: length 2.2
  TOP w0.254: C15.1 26.18,14.87 R19.1 26.17,14.86 U5.7
UNNAMED_5_IND_I56_N2: length 1.4
  TOP w0.203: 27.07,11.05 U5.4 27.29,11.78 27.59,11.49
UNNAMED_5_LINLT8410X_I52_FBP: length 2.6
  TOP w0.254: R20.1 25.11,14.8 R19.2 25.17,14.64 25.72,14.09 U5.8
UNNAMED_6_CAP_I7_N1: length 8.6
  TOP w0.203: U7.5 v1(52.66,22.95)
  BOTTOM w0.203: R28.2 52.66,19.75 v1(52.66,22.95) ; R28.2 54.72,19.74 JP7.1 ; R28.2 52.67,18.88 53.02,18.53 C19.1 C18.1
UNNAMED_6_ICSHT3X_I6_ADDR: length 3.8
  TOP w0.203: v1(56.69,21.88) 56.62,21.95 U7.2
  BOTTOM w0.203: JP7.2 55.6,20.57 55.86,20.83 55.86,21.62 56.12,21.88 v1(56.69,21.88)

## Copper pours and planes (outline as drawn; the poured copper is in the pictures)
1V8_VCCA on TOP: 12.48,12.93 12.3,13 12.23,13.18 12.23,15.14 12.3,15.32 12.48,15.39 15,15.39 15.18,15.32 15.25,15.14 15.25,13.18 15.18,13 15,12.93
1V8_VDD on TOP: 16.3,12.93 16.12,13 16.04,13.18 16.04,15.14 16.12,15.32 16.3,15.39 18.81,15.39 18.99,15.32 19.07,15.14 19.07,13.18 18.99,13 18.81,12.93
1V8_VDD on BOTTOM: 56.34,25.74 56.52,25.82 56.59,26 56.59,26.73 56.52,26.91 56.34,26.99 54.46,26.99 54.28,26.91 54.21,26.73 54.21,26 54.28,25.82 54.46,25.74
3V3_SUPPLY on TOP: 21.47,6.76 21.47,4.69 21.46,4.64 21.43,4.6 21.35,4.6 20.7,3.95 20.67,3.9 20.66,3.86 20.66,1.27 22.86,1.27 22.86,9.27 22.83,9.35 22.74,9.39 21.99,9.39 21.81,9.32 21.73,9.14 21.73,7.03
3V3_SUPPLY on BOTTOM: 56.34,27.51 56.52,27.58 56.59,27.76 56.59,29.68 56.52,29.86 56.34,29.93 55.91,29.93 55.73,29.86 55.66,29.68 55.66,27.76 55.73,27.58 55.91,27.51
3V3_SUPPLY on L3_PWR: 1.27,52.07 27.38,52.07 27.38,32.32 27.46,32.14 27.64,32.07 54.58,32.07 56.62,30.02 56.62,20.5 47.82,11.7 23.22,11.7 23.04,11.62 22.96,11.44 22.96,1.27 1.27,1.27 1.27,32.19 0.65,32.19 0.65,44.93 1.27,44.93
5V_SUPPLY on TOP: 25.65,10.64 25.62,10.6 25.61,10.55 25.61,9.8 24.67,8.95 24.67,7.26 25.61,6.4 25.61,1.27 23.37,1.27 23.37,10.7 23.39,10.8 23.45,10.88 24.56,11.99 24.6,12.02 24.65,12.03 26.17,12.03 26.26,11.99 26.3,11.9 26.3,11.34 26.29,11.29 26.26,11.25
5V_SUPPLY on TOP: 31.5,42.22 31.59,42.18 31.62,42.09 31.62,41.12 31.59,41.03 31.5,41 29.42,41 29.33,41.03 29.29,41.12 29.29,42.09 29.33,42.18 29.42,42.22
5V_SUPPLY on L3_PWR: 28.35,52.07 65.08,52.07 69.21,52.07 69.21,1.27 56.57,1.27 56.57,1.27 23.17,1.27 23.17,11.24 23.25,11.42 23.43,11.49 45.16,11.49 56.57,22.9 56.57,30.81 54.79,32.59 28.6,32.59 28.42,32.66 28.35,32.84 ; 1 cut-out
6V_VLED on TOP: 26.94,13.44 26.94,13.86 26.95,13.91 26.98,13.95 27.25,14.23 27.29,14.26 27.34,14.27 27.68,14.27 27.73,14.28 27.77,14.3 28.5,15.03 34.34,15.03 34.72,14.65 34.72,11.81 34.34,11.43 30.23,11.43 29.09,12.57 29.09,13.31 29.05,13.4 28.96,13.44 26.94,13.44
6V_VLED on BOTTOM: 57.85,26.47 57.67,26.54 57.6,26.72 57.6,28.57 57.67,28.75 57.85,28.83 58.33,28.83 58.51,28.75 58.59,28.57 58.59,26.72 58.51,26.54 58.33,26.47
GND on TOP: 1.27,52.07 65.08,52.07 69.21,52.07 69.21,1.27 65.08,1.27 1.27,1.27 1.27,32.19 0.65,32.19 0.65,44.93 1.27,44.93 ; 3 cut-outs
GND on BOTTOM: 1.27,52.07 65.84,52.07 69.21,52.07 69.21,1.27 65.84,1.27 1.27,1.27 1.27,32.19 0.65,32.19 0.65,35.49 2.8,35.49 2.41,35.88 0.65,35.88 0.65,36.59 2.41,36.59 2.8,36.98 0.65,36.98 0.65,44.93 1.27,44.93 ; 3 cut-outs
GND on L2_GND: 1.27,52.07 61.78,52.07 69.21,52.07 69.21,1.27 61.78,1.27 1.27,1.27 1.27,32.19 0.65,32.19 0.65,44.93 1.27,44.93
UNNAMED_5_IND_I56_N2 on TOP: 27.14,5.6 27.14,6.4 28.08,7.26 28.08,8.95 26.98,9.95 26.95,9.99 26.94,10.04 26.94,11.9 26.98,11.99 27.07,12.03 27.14,12.03 27.19,12.02 27.23,11.99 29.22,10 29.25,9.96 29.26,9.91 29.26,6.3 29.25,6.25 29.22,6.21 28.65,5.64 28.61,5.61 28.56,5.6

Small or netless copper shapes (teardrops, artwork), in the pictures only: 1 on TOP, 3 on L3_PWR

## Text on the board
Ref Des/Silkscreen Bottom: GND | 08-059732 REV B Z | EVAL-CN0537-ARDZ | SECONDARY SIDE
User.Comments: GND | C | A | 4.    RoHS COMPLIANCE: ASSEMBLY VENDOR SHOULD ASSURE COMPLIANCE | 5.    DEFAULT PIN CONNECTION (SOLDER BLOB) FOR THE FOLLOWING 2-PIN SMD JUMPER(S) ONLY: | 6.    ASSEMBLY VENDOR SHOULD PUT ON CHAMBER WITH RIVETS (MPN: 90218A214). | 7.    ASSEMBLY VENDOR SHOULD NOT CUT EXCESS LEADS OF ARDUINO HEADERS P1, P2, P3 & P4. | * JP3, JP4, JP5, JP6, JP12, JP14, JP16, JP18, & JP19 | WITH LEAD-FREE AND RoHS PCB ASSEMBLY STANDARDS (EU RoHS | DIRECTIVE 2002/95/EC). | SEE DETAIL | SEE NOTE 6
Ref Des/Silkscreen Top: GND | C | A | 08-059732 REV B Z | EVAL-CN0537-ARDZ | PRIMARY SIDE
PAGE_OUTLINE: B | PER ECR-094474 | 18MAY20 | A.UY
DIMENSION: - | " " | REF | DIA MAX
User.12: 3 | 1 | 2 | SEE DETAIL B | DETAIL B
User.13: PINS 2 & 3 | JP7 - | ASSEMBLY NOTE: | 1.    DEFAULT PIN CONNECTION (SOLDER BLOB) FOR THE FOLLOWING 3-PIN SMD JUMPER(S) ONLY: | 1 | 3 | 2 | JP7
User.15: ROHS COMPLIANCE NOTE: | HOMOGENOUS MATERIALS IN THIS BOARD SHALL BE COMPLIANT | THE EU RoHS DIRECTIVE 2002/95/EC
User.17: L2 GND | 08-      -07
User.18: L3 PWR | 08-      -08
User.45: FIGURE | SIZE | 0.203 | 0.254 | 0.889 | 1.016 | 1.143 | 1.97 | 3.92 | DRILL CHART: TOP to BOTTOM | FINISHED HOLES IN MILLIMETERS | PLATED | NON-PLATED | QTY | 6 | 198 | 2 | 7 | 42 | TOLERANCE/NOTES
